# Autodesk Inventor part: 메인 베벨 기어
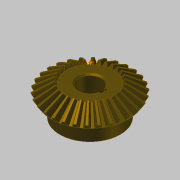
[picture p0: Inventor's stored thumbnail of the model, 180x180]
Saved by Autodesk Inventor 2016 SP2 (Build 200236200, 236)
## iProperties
Created: 2016-04
Part Number: 메인 베벨 기어
Material: 강철, 탄소
Document SubType Name: Modeling
Designer: mdu
Categories: <?xml version="1.0" encoding="UTF-16"?> <MemberInstance><Categories><FamilyTemplate><FamilyTemplateParameter ValueType="xs:double" Id="1" ObjectReferenceKey="da
Mass: 269.926 g
Surface Area: 108.837 cm^2
Volume: 34.2981 cm^3
Density: 7.87 g/cm^3
Appearance: 얼룩무늬
CustomPartVersion: 1
Author: mdu
Revision Number: 1
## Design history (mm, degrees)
node "맨 위 점"
node "메쉬 평면2"
sketch "톱니 본체 스케치"
  geometry: L1 (0, 0)-(28.669, -21.997); L2 (28.669, -21.997)-(31.109, -18.336); L3 (31.109, -18.336)-(0, 0); L4 (30, -20)-(0, 0); L5 (17.219, -13.212)-(18.685, -11.013); L6 (28.669, -21.997)-(17.219, -13.212); L7 (31.109, -18.336)-(18.685, -11.013); L8 (0, -39.387)-(0, 6.564) reference; L9 (0, -20)-(31.109, -20)
  constraints: 16 end point, 4 point on line, 3 perpendicular, 2 collinear, 1 horizontal alignment, 1 vertical alignment
  dimensions: "d0" = 60 diameter of L4.start L8 (= da_de); "d1" = 57.33744 diameter of L1.end L8 (= da_dfe); "d2" = 62.2188 diameter of L2.end L8 (= da_dae); "d3" = 14.4 distance between parallel lines of L2 L5 (= da_b); "d4" = 18.3359 vertical distance of L2.end L1.start (= da_ve)
revolve "톱니 본체" sketch "톱니 본체 스케치" stored, may be unused: angle "d5" = 90 deg
node "시작점"
node "톱니 평면"
sketch "시작 스케치"
  geometry: L1 (0, -23.505)-(0, 10.645) reference; L2 (-0.709, -2.928)-(0.709, -2.928); A1 r 19.188 centre (-19.457, -7.014) between (-0.709, -2.928) and (-3.232, 3.229); A2 r 19.188 centre (19.457, -7.014) between (3.232, 3.229) and (0.709, -2.928); A3 r 57.403 centre (0, -54.083) between (3.232, 3.229) and (-3.232, 3.229); 1 further point
  constraints: 6 point on circle, 3 centre point, 3 symmetric about line, 2 end point, 1 coincident, 1 perpendicular, 1 other
  dimensions: "d7" = 19.18795 radius of A1 (= fd_rr); "d8" = 19.45712 horizontal distance of point (0, -54.083) A1.centre (= fd_x); "d9" = 47.06905 vertical distance of point (0, -54.083) A1.centre (= fd_y); "d57" = 57.40327 radius of A3 (= 0.5 x fd_dva + 0.3 x da_he); "d58" = 51.15527 distance from line of A3.centre L2 (= 0.5 x fd_dva - 1.12 x da_he)
node "끝점"
  node "끝 평면"
sketch "3D 스케치 오른쪽"
  node "Helical Curve Right" dims "d65" = 229.90621 (computed from da_dm, da_delta, da_beta), "d66" = 31.5, "d67" = 60 (= da_de), "d68" = -9.82794 (= -da_delta), "d69" = 8.10972 (computed from fd_loft, da_delta)
node "끝 평면 오른쪽"
sketch "끝 스케치 오른쪽"
  geometry: L1 (0, -41.54)-(0, 13.178) reference; L2 (-0.422, -1.69)-(0.422, -1.69); A1 r 11.427 centre (-11.587, -4.123) between (-0.422, -1.69) and (-1.925, 1.977); A2 r 11.427 centre (11.587, -4.123) between (1.925, 1.977) and (0.422, -1.69); A3 r 34.184 centre (0, -32.153) between (1.925, 1.977) and (-1.925, 1.977); 1 further point
  constraints: 6 point on circle, 3 centre point, 3 symmetric about line, 2 end point, 1 coincident, 1 perpendicular, 1 other
  dimensions: "d70" = 11.58699 horizontal distance of A3.centre A1.centre (computed from fd_x, fd_ratio); "d71" = 28.03028 vertical distance of point (0, -32.153) A1.centre (computed from fd_y, fd_ratio); "d72" = 11.4267 radius of A1 (computed from fd_rr, fd_ratio); "d73" = 30.46369 distance from line of point (0, -32.153) L2 (computed from d58, fd_ratio); "d74" = 34.18446 radius of A3 (computed from d57, fd_ratio)
feature "로프트 오른쪽" sketch "끝 스케치 오른쪽" dims "d75" = 0, "d77" = 0, "d79" = 0, "d80" = 90 deg, "d85" = 20, "d92" = 90 deg, "d93" = 90 deg, "da_teethtype" = 0 [user parameter]
sketch "3D 스케치 왼쪽"
  node "Helical Curve Left" dims "d26" = 229.90621 (computed from da_dm, da_delta, da_beta), "d27" = 8.10972 (computed from fd_loft, da_delta), "d28" = 60 (= da_de), "d29" = -9.82794 (= -da_delta)
node "끝 평면 왼쪽"
sketch "끝 스케치 왼쪽" dims "d56" = 10.3728 (derived)
  geometry: L1 (0, -43.753)-(0, 15.405) reference; L2 (-0.422, -1.678)-(0.422, -1.678); A1 r 11.427 centre (-11.587, -4.111) between (-0.422, -1.678) and (-1.925, 1.988); A2 r 11.427 centre (11.587, -4.111) between (1.925, 1.988) and (0.422, -1.678); A3 r 34.184 centre (0, -32.142) between (1.925, 1.988) and (-1.925, 1.988); 2 further points; 1 other entity
  constraints: 6 point on circle, 3 centre point, 3 symmetric about line, 2 end point, 1 coincident, 2 other
  dimensions: "d30" = 11.4267 radius of A1 (computed from fd_rr, fd_ratio); "d31" = 11.58699 horizontal distance of point (0, -32.142) A1.centre (computed from fd_x, fd_ratio); "d32" = 28.03028 vertical distance of A1.centre point (0, -32.142) (computed from fd_y, fd_ratio); "d61" = 34.18446 radius of A3 (computed from d57, fd_ratio); "d62" = 30.46369 distance from line of point (0, -32.142) L2 (computed from d58, fd_ratio)
feature "로프트 왼쪽" sketch "끝 스케치 왼쪽" dims "d35" = 0, "d37" = 0, "d39" = 0, "d40" = 90 deg, "d84" = 10, "d90" = 90 deg, "d91" = 90 deg, "da_teethtype" = 0 [user parameter]
sketch "본체 스케치"
  geometry: L1 (0, -35.038)-(0, -19.531) reference; L2 (28.669, -21.997)-(17.219, -13.212) reference; L3 (17.219, -13.212)-(0, -13.212); L4 (28.669, -21.997)-(0, -21.997)
  constraints: 4 end point, 2 perpendicular, 2 point on line
revolve "본체 고정" sketch "본체 스케치" stored, may be unused: angle "d46" = 90 deg
feature "피치 지름" dims angle "d47" = 90 deg
sketch "스케치8"
  geometry: C1 r 22.5 at (0, 0); 1 further point
  constraints: 1 centre point, 1 coincident
  dimensions: "d94" = 45 diameter of C1
extrude "돌출1" join sketch "스케치8" distance "d95" = 13; taper "d96" = 0 deg
sketch "스케치9"
  geometry: 1 further point
hole "구멍1" sketch "스케치9" at (0, 0) diameter "d97" = 17; stored, may be unused: countersink angle "d101" = 90 deg, drill point angle "d103" = 118 deg; dims "d98" = 6, "d99" = 4, "d100" = 2, "d102" = 8
sketch "스케치10"
  geometry: L1 (8.124, 2.5)-(10.8, 2.5); L2 (10.8, 2.5)-(10.8, -2.5); L3 (10.8, -2.5)-(8.124, -2.5); A1 r 8.5 centre (0, 0) between (8.124, 2.5) and (8.124, -2.5) reference; 1 further point
  constraints: 6 end point, 2 parallel, 2 point on circle, 1 horizontal, 1 perpendicular
  dimensions: "d104" = 5 distance of L1.end L2.end; "d112" = 19.3 dimension on A1 L2
extrude "돌출2" cut sketch "스케치10" stored distance "d106" = 10; taper "d107" = 0 deg
chamfer "모따기1" distance "d108" = 1; stored, may be unused: second distance "d109" = 2, angle "d110" = 45 deg
fillet "모깎기1" dims "d111" = 2
body "Solid1"
feature "로프트" dims "d17" = 0, "d18" = 90 deg, "d19" = 0, "d20" = 90 deg, "d89" = 0, "da_teethtype" = 0 [user parameter]
pattern_circular "원형 패턴" dims angle "d22" = 360 deg, "d88" = 0, "da_teethtype" = 0 [user parameter]
pattern_circular "원형 패턴 오른쪽" dims angle "d82" = 360 deg, "da_teethtype" = 0 [user parameter]
pattern_circular "원형 패턴 왼쪽" dims angle "d42" = 360 deg, "da_teethtype" = 0 [user parameter]
sketch "끝 스케치"
  geometry: L1 (0, -15.359)-(0, 6.983) reference; L2 (-0.422, -1.69)-(0.422, -1.69); A1 r 11.427 centre (-11.587, -4.123) between (-0.422, -1.69) and (-1.925, 1.977); A2 r 11.427 centre (11.587, -4.123) between (1.925, 1.977) and (0.422, -1.69); A3 r 34.184 centre (0, -32.153) between (1.925, 1.977) and (-1.925, 1.977); 1 further point
  constraints: 6 point on circle, 3 centre point, 3 symmetric about line, 2 end point, 1 coincident, 1 other
  dimensions: "d12" = 11.4267 radius of A1 (computed from fd_rr, fd_ratio); "d15" = 11.58699 horizontal distance of A1.centre point (0, -32.153) (computed from fd_x, fd_ratio); "d16" = 28.03028 vertical distance of A1.centre point (0, -32.153) (computed from fd_y, fd_ratio); "d59" = 34.18446 radius of A3 (computed from d57, fd_ratio); "d60" = 30.46369 distance from line of A3.centre L2 (computed from d58, fd_ratio)
sketch "Sketch6"
  geometry: L1 (30, -20)-(0, 0) reference; L2 (0, -37.8)-(0, 6.3) reference
body "Srf1"
other parameters: "da_b" = 14.4 [user parameter; used in 2 equation terms], "da_de" = 60 [user parameter; used in 4 equation terms], "da_dae" = 62.2188 [user parameter; used in 2 equation terms], "da_dfe" = 57.33744 [user parameter; used in 1 equation term], "da_le" = 36.05551 [user parameter; used in 1 equation term], "da_omega" = 90 deg [user parameter; used in 1 equation term], "da_beta" = 0 [user parameter; used in 2 equation terms], "da_delta" = 9.82794 [user parameter; used in 8 equation terms], "da_alpha" = 20 deg [user parameter; used in 2 equation terms], "da_he" = 4.4 [user parameter; used in 4 equation terms], "da_ve" = 18.3359 [user parameter; used in 1 equation term], "fd_dv" = 108.16654 (computed from da_de, da_delta) [user parameter; used in 1 equation term], "fd_dva" = 112.16654 (computed from da_dae, da_delta) [user parameter; used in 3 equation terms], "fd_dvb" = 101.6433 (computed from fd_dv, da_alpha) [user parameter; used in 2 equation terms], "da_zv" = 540.83269 [user parameter; used in 1 equation term], "fd_loft" = 14.62 (= da_b + 0.05 x da_he) [user parameter; used in 4 equation terms], "fd_ratio" = 5.95514 (computed from da_le, fd_loft) [user parameter; used in 15 equation terms], "fd_rr" = 19.18795 (computed from fd_dd, fd_dvb) [user parameter; used in 6 equation terms], "fd_angle" = 0.29367 (computed from da_zv) [user parameter; used in 4 equation terms], "fd_x1" = 1.58802 (computed from da_dvw, fd_angle) [user parameter; used in 1 equation term], "fd_y1" = 54.05995 (computed from da_dvw, fd_angle) [user parameter; used in 1 equation term], "fd_x2" = 17.8691 (computed from fd_rr, fd_angle2, fd_angle) [user parameter; used in 1 equation term], "fd_y2" = 6.9909 (computed from fd_rr, fd_angle2, fd_angle) [user parameter; used in 1 equation term], "fd_x" = 19.45712 (= fd_x1 + fd_x2) [user parameter; used in 4 equation terms], "fd_y" = 47.06905 (= fd_y1 - fd_y2) [user parameter; used in 4 equation terms], "fd_angle2" = 3.43555 (computed from fd_dvb, fd_dd, da_alpha) [user parameter; used in 2 equation terms], "fd_dd" = 108.64654 (= fd_dva - 0.8 x da_he) [user parameter; used in 2 equation terms], "da_dvw" = 108.16654 [user parameter; used in 2 equation terms], "d11" = 14.62 (= fd_loft), "da_dm" = 48.01848 [user parameter; used in 2 equation terms], "da_x" = 0 [user parameter], "da_m" = 2 [user parameter], "d48" = 0, "d49" = 0, "d50" = 90 deg (= da_omega), "d51" = 6 deg (computed from da_z), "d52" = 0, "d53" = 0, "d54" = 0
